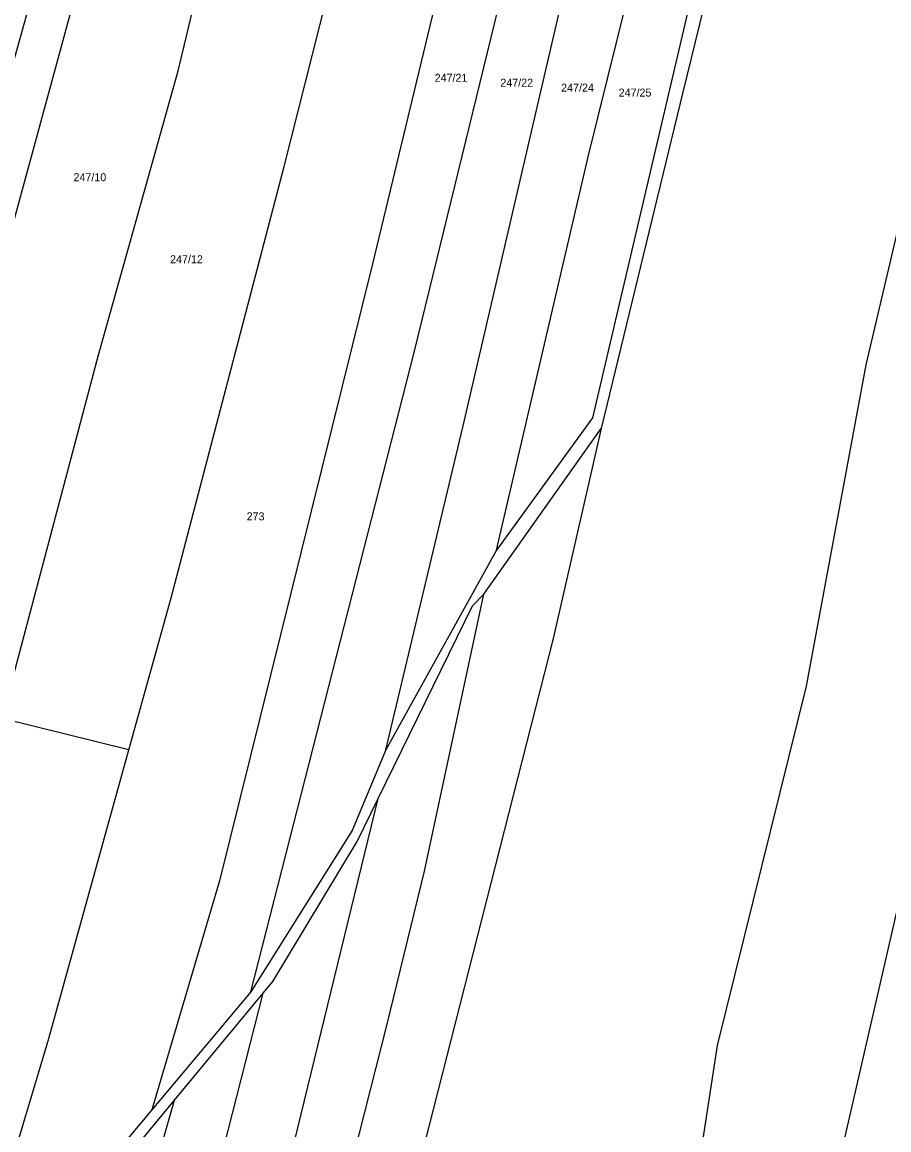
# Model space of a CAD drawing. Extents: x -744566 to -741843, y -1128407 to -1126744.
# Drawn here: x -743260.5 to -743076.5, y -1128024.5 to -1127789.3 of the extents above; entities that cross this region are included whole.
import ezdxf

# ---------------------------------------------------------------- set-up
doc = ezdxf.new("R2010")
doc.units = 0
doc.layers.add('Hranice parcel', color=7, linetype='Continuous')
doc.layers.add('Parcelní čísla', color=7, linetype='Continuous')

msp = doc.modelspace()

# ---------------------------------------------------------------- linework, layer by layer
at = {"layer": 'Hranice parcel'}
for p, q in [((-743162.47, -1127910.78), (-743137.57, -1127875.6)), ((-743159.84, -1127901.41), (-743183.31, -1127943.86)), ((-743237.87, -1127943.87), (-743264.74, -1127937.21)), ((-743211.94, -1127995.24), (-743232.97, -1128020.31)), ((-743228.15, -1128018.27), (-743209.35, -1127995.55)), ((-743232.97, -1128020.31), (-743274.12, -1128069.36))]:
    msp.add_line(p, q, dxfattribs=at)
for points in [[(-743136.68, -1127662.01), (-743145.81, -1127680.82), (-743155.72, -1127714.23), (-743186.13, -1127840.64), (-743218.63, -1127971.66), (-743232.97, -1128020.31)], [(-743211.94, -1127995.24), (-743177.21, -1127859.16), (-743152.4, -1127757.44), (-743146.1, -1127728.25), (-743135.93, -1127692.62), (-743130.84, -1127678.65), (-743124.37, -1127665.91)], [(-743237.87, -1127943.87), (-743228.87, -1127911.59), (-743204.89, -1127820), (-743186.75, -1127748.28), (-743176.72, -1127702.48), (-743165.44, -1127669.87)], [(-743183.31, -1127943.86), (-743166.85, -1127875.07), (-743131.1, -1127720.81), (-743124.32, -1127698.36), (-743119.23, -1127686.62), (-743112.44, -1127675.65)], [(-743264.74, -1127937.21), (-743244.37, -1127860.25), (-743227.42, -1127799.64), (-743205.44, -1127708.1), (-743196.8, -1127679.29)], [(-743159.84, -1127901.41), (-743140.31, -1127817.95), (-743115.61, -1127717.91), (-743107.65, -1127696.37), (-743101.11, -1127685.19)], [(-743225.59, -1127692.63), (-743249.75, -1127785.46), (-743287.33, -1127923.2), (-743297.04, -1127954.42)], [(-743089.62, -1127695.12), (-743093.02, -1127699.07), (-743102.39, -1127722.13), (-743112.61, -1127758.91), (-743139.42, -1127873.34), (-743159.84, -1127901.41)], [(-743086.91, -1127697.47), (-743090.95, -1127700.36), (-743100.45, -1127723.29), (-743120.32, -1127804.45), (-743137.57, -1127875.6)], [(-743235.82, -1127698.28), (-743249, -1127749.54), (-743300.05, -1127932.95), (-743303.92, -1127943.26)], [(-743134.48, -1128101.6), (-743116.84, -1128032.47), (-743112.87, -1128006.6), (-743093.99, -1127930.3), (-743081.3, -1127862.06), (-743057.88, -1127762.39), (-743049.21, -1127739.41)], [(-743103, -1128100.87), (-743064.96, -1127935.44), (-743045.29, -1127844.24), (-743032.09, -1127792.31), (-743025.38, -1127776.65)], [(-743137.57, -1127875.6), (-743147.81, -1127920.19), (-743185.51, -1128068.25), (-743194.5, -1128103)], [(-743208.7, -1128103.33), (-743183.09, -1128002.36), (-743175.1, -1127969.59), (-743162.47, -1127910.78)], [(-743184.94, -1127954.19), (-743164.89, -1127913.26), (-743162.47, -1127910.78)], [(-743274.12, -1128069.36), (-743254.82, -1128005.17), (-743237.87, -1127943.87)], [(-743183.31, -1127943.86), (-743190.45, -1127960.97), (-743211.94, -1127995.24)], [(-743223.91, -1128103.68), (-743211.98, -1128065), (-743184.94, -1127954.19)], [(-743209.35, -1127995.55), (-743207.28, -1127993.05), (-743189.39, -1127963.29), (-743184.94, -1127954.19)], [(-743239.47, -1128104.04), (-743219.54, -1128035.53), (-743209.35, -1127995.55)], [(-743286.03, -1128107.53), (-743261.3, -1128058.36), (-743228.15, -1128018.27)], [(-743254.5, -1128104.39), (-743239.6, -1128058.4), (-743228.15, -1128018.27)]]:
    msp.add_lwpolyline(points, dxfattribs=at)

# ---------------------------------------------------------------- texts
at = {"layer": 'Parcelní čísla'}
for s, p in [('247/21', (-743172.94, -1127801.99)), ('247/22', (-743158.99, -1127803.03)), ('247/24', (-743146.08, -1127804.08)), ('247/25', (-743133.87, -1127805.13)), ('247/10', (-743249.61, -1127823.1)), ('247/12', (-743229.1, -1127840.52)), ('273', (-743212.85, -1127895.11))]:
    msp.add_text(s, height=1.7, dxfattribs=at).set_placement(p)

doc.saveas('drawing.dxf')
